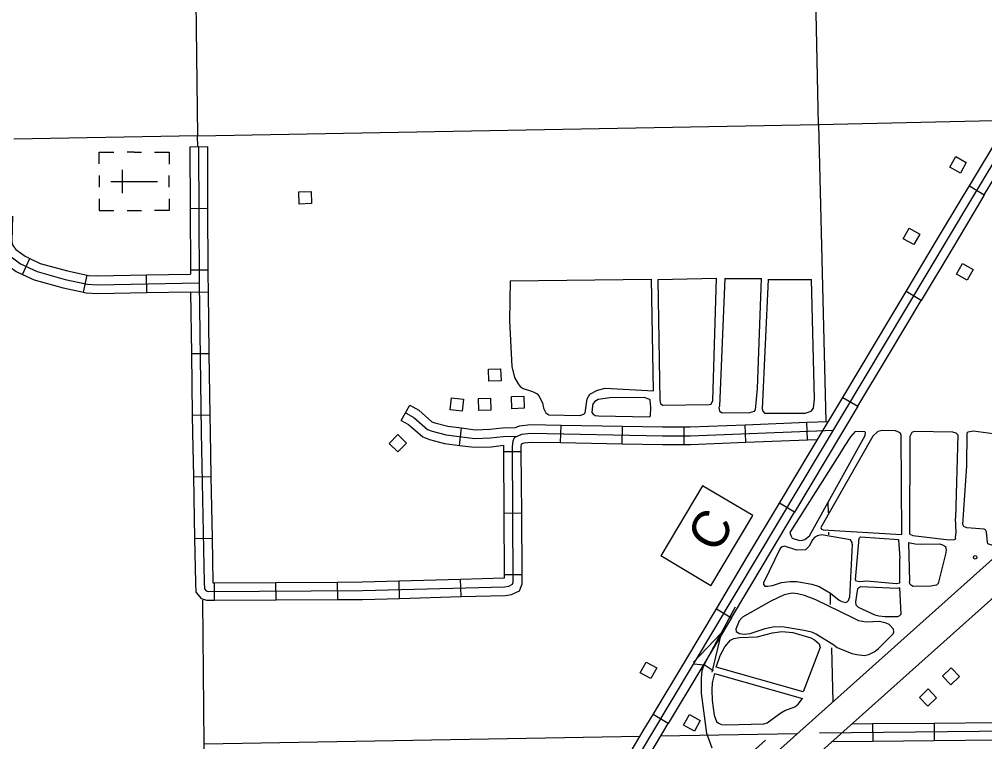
# Model space of a CAD drawing. Extents: x 1084508 to 1142749, y 1057638 to 1093403.
# Drawn here: x 1097414 to 1100010, y 1070508 to 1072452 of the extents above; entities that cross this region are included whole.
import ezdxf

# ---------------------------------------------------------------- set-up
doc = ezdxf.new("R2010")
doc.units = 0
for name, color, linetype in [('Level 15', 7, 'Continuous'), ('Level 31', 7, 'Continuous'), ('Level 32', 7, 'Continuous'), ('Level 35', 7, 'Continuous'), ('Level 43', 7, 'Continuous'), ('Level 5', 7, 'Continuous'), ('Level 56', 7, 'Continuous'), ('Level 57', 7, 'Continuous'), ('Level 58', 7, 'Continuous')]:
    doc.layers.add(name, color=color, linetype=linetype)

msp = doc.modelspace()

# ---------------------------------------------------------------- linework, layer by layer
at = {"layer": 'Level 15'}
for points in [[(1102254.8, 1073114.2), (1102246.6, 1073054.1), (1102235.2, 1073013), (1102230.6, 1072998.9), (1102210.8, 1072969.7), (1102197.7, 1072955.1), (1102173.8, 1072922.9), (1102155, 1072900), (1102143.6, 1072888.3), (1102116.9, 1072867), (1101851.5, 1072624), (1101364.1, 1072185.3), (1100217.6, 1071166.4), (1099385.1, 1070422.3)], [(1099437.4, 1070363.8), (1100269.9, 1071107.8), (1101416.4, 1072126.8), (1101904.3, 1072565.9), (1102168, 1072807.4), (1102196.3, 1072830.1), (1102213.4, 1072847.6), (1102235.6, 1072874.5), (1102258.6, 1072905.4), (1102272.7, 1072921.2), (1102301.9, 1072964.1), (1102310.4, 1072990.5), (1102323.6, 1073038.2), (1102332.6, 1073103.6)]]:
    msp.add_lwpolyline(points, dxfattribs=at)
at = {"layer": 'Level 31'}
for p, q in [((1099968.7, 1072003.9), (1100009, 1071979.6)), ((1099838.9, 1071695.2), (1099798.5, 1071719.4)), ((1099628.4, 1071434.9), (1099668.9, 1071410.7)), ((1099498.8, 1071126.2), (1099458.4, 1071150.4)), ((1099458.4, 1071150.4), (1099458.4, 1071150.4)), ((1099288.3, 1070865.9), (1099328.7, 1070841.7)), ((1099243.7, 1070699.4), (1099243.7, 1070699.4)), ((1099158.7, 1070557.2), (1099118.2, 1070581.3))]:
    msp.add_line(p, q, dxfattribs=at)
for points in [[(1098799.7, 1069999.4), (1099112.2, 1070525.3), (1099972.3, 1071964.3), (1100614.4, 1073030.4)], [(1099968.7, 1072003.9), (1100054.2, 1072145.9)], [(1100009, 1071979.6), (1100094.5, 1072121.6)], [(1099883.5, 1071861.6), (1099952.2, 1071976.4), (1099968.7, 1072003.9)], [(1100009, 1071979.6), (1099992.5, 1071952.2), (1099924, 1071837.5)], [(1099798.5, 1071719.4), (1099883.5, 1071861.6)], [(1099924, 1071837.5), (1099838.9, 1071695.2)], [(1099713.5, 1071577.1), (1099798.5, 1071719.4)], [(1099753.9, 1071553), (1099838.9, 1071695.2)], [(1099628.4, 1071434.9), (1099713.5, 1071577.1)], [(1099668.9, 1071410.7), (1099753.9, 1071553)], [(1099543.4, 1071292.6), (1099628.4, 1071434.9)], [(1099668.9, 1071410.7), (1099583.8, 1071268.4)], [(1099458.4, 1071150.4), (1099543.4, 1071292.6)], [(1099583.8, 1071268.4), (1099498.8, 1071126.2)], [(1099373.3, 1071008.1), (1099458.4, 1071150.4)], [(1099413.8, 1070983.9), (1099498.8, 1071126.2)], [(1099288.3, 1070865.9), (1099373.3, 1071008.1)], [(1099328.7, 1070841.7), (1099413.8, 1070983.9)], [(1099203.3, 1070723.6), (1099288.3, 1070865.9)], [(1099328.7, 1070841.7), (1099243.7, 1070699.4)], [(1099118.2, 1070581.3), (1099203.3, 1070723.6)], [(1099243.7, 1070699.4), (1099158.7, 1070557.2)], [(1099033.4, 1070438.9), (1099091.9, 1070537.3), (1099118.2, 1070581.3)], [(1099073.9, 1070414.8), (1099132.4, 1070513.2), (1099158.7, 1070557.2)]]:
    msp.add_lwpolyline(points, dxfattribs=at)
at = {"layer": 'Level 32'}
for p, q in [((1097872.4, 1072109.2), (1097919.4, 1072109.4)), ((1097873.1, 1071943.4), (1097920.1, 1071943.6)), ((1097422.5, 1071765.5), (1097442.3, 1071808.2)), ((1097586, 1071717.5), (1097595.9, 1071763.5)), ((1097757, 1071717), (1097756.1, 1071764.1)), ((1097873.8, 1071777.7), (1097920.9, 1071777.9)), ((1097874.3, 1071718.2), (1097921.3, 1071718.8)), ((1097876.6, 1071552.4), (1097923.7, 1071553.1)), ((1098440.7, 1071372.7), (1098463.8, 1071413.7)), ((1097878.9, 1071386.7), (1097926, 1071387.4)), ((1098597.3, 1071305.7), (1098603.1, 1071352.4)), ((1098869.6, 1071313.1), (1098870.5, 1071360.2)), ((1099035.3, 1071310.1), (1099036.2, 1071357.2)), ((1099201.5, 1071308.2), (1099201.4, 1071355.3)), ((1099368, 1071314.1), (1099366.1, 1071361.1)), ((1099533.6, 1071320.7), (1099531.7, 1071367.7)), ((1098763.8, 1071288.6), (1098716.7, 1071288.3)), ((1097881.8, 1071220.9), (1097928.8, 1071221.8)), ((1098764.8, 1071122.9), (1098717.7, 1071122.6)), ((1097884.9, 1071055.2), (1097931.9, 1071056.1)), ((1098765.7, 1070957.2), (1098718.6, 1070956.9)), ((1097938.5, 1070888.9), (1097938.3, 1070936)), ((1098104.3, 1070889.9), (1098104, 1070937)), ((1098270, 1070890.9), (1098269.7, 1070938)), ((1098436.2, 1070894.1), (1098434.9, 1070941.1)), ((1098601.9, 1070898.6), (1098600.6, 1070945.7)), ((1099708.3, 1070556), (1099708.8, 1070508.9)), ((1099874, 1070557.7), (1099874.5, 1070510.7))]:
    msp.add_line(p, q, dxfattribs=at)
for points in [[(1097872.4, 1072109.2), (1097873.1, 1071943.4)], [(1097895.9, 1072109.3), (1097897.5, 1071743.2)], [(1097919.4, 1072109.4), (1097920.1, 1071943.6)], [(1097873.1, 1071943.4), (1097873.8, 1071777.7)], [(1097920.1, 1071943.6), (1097920.9, 1071777.9)], [(1097348.6, 1071923.8), (1097346.2, 1071853.2), (1097348, 1071838.6), (1097354.3, 1071820.4), (1097371.5, 1071798.7), (1097404.9, 1071773.7), (1097422.5, 1071765.5)], [(1097395.6, 1071922.3), (1097393.4, 1071855.4), (1097394.2, 1071849.3), (1097396.2, 1071843.3), (1097404.6, 1071832.7), (1097429.1, 1071814.4), (1097442.3, 1071808.2)], [(1097388, 1071815.7), (1097417, 1071794.1), (1097461.6, 1071773.3), (1097537.3, 1071752), (1097596.7, 1071739.3), (1097623.1, 1071738), (1097897.5, 1071743.2), (1097903.1, 1071340.6), (1097910.6, 1070936.5), (1097911.5, 1070919.9), (1097916.4, 1070914.1), (1097921.2, 1070912.4), (1098336.5, 1070914.9), (1098718.9, 1070925.4), (1098730.4, 1070927), (1098740, 1070931.8), (1098742.3, 1070937.8), (1098740.2, 1071301.6), (1098741.5, 1071318.3), (1098744.1, 1071325), (1098747.1, 1071327.6), (1098765.4, 1071335.4), (1098789.8, 1071338.2), (1099143.6, 1071331.7), (1099218.6, 1071331.7), (1099603.6, 1071347)], [(1097442.3, 1071808.2), (1097469.8, 1071795.4), (1097543, 1071774.9), (1097595.9, 1071763.5)], [(1097422.5, 1071765.5), (1097453.4, 1071751.1), (1097531.7, 1071729.1), (1097586, 1071717.5)], [(1097595.9, 1071763.5), (1097599.8, 1071762.7), (1097623.5, 1071761.5), (1097756.1, 1071764.1)], [(1097756.1, 1071764.1), (1097873.8, 1071766.3)], [(1097873.8, 1071777.7), (1097873.8, 1071766.3)], [(1097920.9, 1071777.9), (1097920.7, 1071767.2)], [(1097920.7, 1071767.2), (1097921.3, 1071718.8)], [(1097586, 1071717.5), (1097593.7, 1071715.8), (1097622.8, 1071714.4), (1097757, 1071717)], [(1097757, 1071717), (1097874.3, 1071719.2), (1097874.3, 1071718.2)], [(1097874.3, 1071718.2), (1097876.6, 1071552.4)], [(1097921.3, 1071718.8), (1097923.7, 1071553.1)], [(1097923.7, 1071553.1), (1097926, 1071387.4)], [(1097876.6, 1071552.4), (1097878.9, 1071386.7)], [(1098463.8, 1071413.7), (1098487.9, 1071400.1), (1098523.4, 1071369.3), (1098531.3, 1071366.3), (1098566.3, 1071357), (1098603.1, 1071352.4)], [(1097878.9, 1071386.7), (1097879.5, 1071340.2), (1097881.8, 1071220.9)], [(1097926, 1071387.4), (1097926.6, 1071341), (1097928.8, 1071221.8)], [(1098440.7, 1071372.7), (1098460.7, 1071361.4), (1098498.9, 1071328.2), (1098517, 1071321.4), (1098557.3, 1071310.7), (1098597.3, 1071305.7)], [(1098452.2, 1071393.2), (1098474.3, 1071380.8), (1098511.1, 1071348.8), (1098524.2, 1071343.9), (1098561.8, 1071333.8), (1098639, 1071324.2), (1098680.7, 1071325.6), (1098714.8, 1071329.3), (1098751.9, 1071330.2)], [(1098603.1, 1071352.4), (1098640.1, 1071347.8), (1098679, 1071349.1), (1098713.2, 1071352.8), (1098748.2, 1071353.7)], [(1098748.2, 1071353.7), (1098759.3, 1071358.4), (1098788.7, 1071361.7), (1098870.5, 1071360.2)], [(1098870.5, 1071360.2), (1099036.2, 1071357.2)], [(1099036.2, 1071357.2), (1099143.8, 1071355.2), (1099201.4, 1071355.3)], [(1099201.4, 1071355.3), (1099218.1, 1071355.3), (1099366.1, 1071361.1)], [(1099366.1, 1071361.1), (1099531.7, 1071367.7)], [(1099531.7, 1071367.7), (1099589.7, 1071370)], [(1099368, 1071314.1), (1099533.6, 1071320.7)], [(1099533.6, 1071320.7), (1099560.8, 1071321.8)], [(1098597.3, 1071305.7), (1098638, 1071300.6), (1098682.4, 1071302.1), (1098716.9, 1071305.9)], [(1098716.7, 1071288.3), (1098716.6, 1071302.5), (1098716.9, 1071305.9)], [(1098763.8, 1071288.6), (1098763.7, 1071300.7), (1098764.4, 1071309.4), (1098771.5, 1071312.4), (1098790.9, 1071314.6), (1098869.6, 1071313.1)], [(1098869.6, 1071313.1), (1099035.3, 1071310.1)], [(1099035.3, 1071310.1), (1099143.4, 1071308.1), (1099201.5, 1071308.2)], [(1099201.5, 1071308.2), (1099219, 1071308.2), (1099368, 1071314.1)], [(1098717.7, 1071122.6), (1098716.7, 1071288.3)], [(1098764.8, 1071122.9), (1098763.8, 1071288.6)], [(1097881.8, 1071220.9), (1097884.9, 1071055.2)], [(1097928.8, 1071221.8), (1097931.9, 1071056.1)], [(1098718.6, 1070956.9), (1098717.7, 1071122.6)], [(1098765.7, 1070957.2), (1098764.8, 1071122.9)], [(1097884.9, 1071055.2), (1097887.1, 1070935.6), (1097888.4, 1070910.7), (1097902.5, 1070894.1), (1097917.1, 1070888.8), (1097938.5, 1070888.9)], [(1097931.9, 1071056.1), (1097934.1, 1070937.3), (1097934.2, 1070936), (1097938.3, 1070936)], [(1098600.6, 1070945.7), (1098716.9, 1070948.9), (1098718.7, 1070949.1), (1098718.6, 1070956.9)], [(1098601.9, 1070898.6), (1098720.9, 1070901.9), (1098737.5, 1070904.3), (1098758.7, 1070914.7), (1098765.9, 1070933.5), (1098765.7, 1070957.2)], [(1097938.3, 1070936), (1098104, 1070937)], [(1098104, 1070937), (1098269.7, 1070938)], [(1098269.7, 1070938), (1098336.1, 1070938.4), (1098434.9, 1070941.1)], [(1098434.9, 1070941.1), (1098600.6, 1070945.7)], [(1097938.5, 1070888.9), (1098104.3, 1070889.9)], [(1098104.3, 1070889.9), (1098270, 1070890.9)], [(1098270, 1070890.9), (1098336.8, 1070891.3), (1098436.2, 1070894.1)], [(1098436.2, 1070894.1), (1098601.9, 1070898.6)], [(1101200, 1070548.2), (1099566.1, 1070531)], [(1099708.3, 1070556), (1099651.8, 1070555.4)], [(1099874, 1070557.7), (1099708.3, 1070556)], [(1100039.8, 1070559.5), (1099874, 1070557.7)], [(1099708.8, 1070508.9), (1099598.4, 1070507.8)], [(1099874.5, 1070510.7), (1099708.8, 1070508.9)], [(1100040.3, 1070512.4), (1099874.5, 1070510.7)]]:
    msp.add_lwpolyline(points, dxfattribs=at)
at = {"layer": 'Level 35'}
for points in [[(1098734.2, 1071748), (1098731.8, 1071640.8), (1098738.1, 1071518), (1098745.7, 1071488.7), (1098755, 1071471.4), (1098760.9, 1071464.1), (1098768.6, 1071459), (1098793.7, 1071450.8), (1098806.1, 1071444.3), (1098811, 1071439.1), (1098820.7, 1071420.3), (1098823.7, 1071406), (1098830.1, 1071393.6), (1098837.8, 1071388.2), (1098921, 1071385.7), (1098932.2, 1071389.6), (1098935.8, 1071393.1), (1098940.8, 1071431.3), (1098948, 1071443.8), (1098969, 1071453.9), (1098989.2, 1071459.3), (1099119.3, 1071452.1), (1099114.3, 1071752.7)], [(1098734.2, 1071748), (1099114.3, 1071752.7)], [(1099131.3, 1071751.9), (1099136.2, 1071426.5), (1099138.4, 1071418.1), (1099143.6, 1071413.6), (1099268.7, 1071415.3), (1099274.6, 1071416.8), (1099279, 1071426), (1099289, 1071755.7)], [(1099131.3, 1071751.9), (1099289, 1071755.7)], [(1099310.7, 1071754.3), (1099296.8, 1071411), (1099295, 1071407.8), (1099297.2, 1071398.1), (1099304.3, 1071393.3), (1099378.6, 1071394), (1099391.3, 1071397.6), (1099393.7, 1071401.1), (1099399.3, 1071459.1), (1099409.5, 1071754.2)], [(1099310.7, 1071754.3), (1099409.5, 1071754.2)], [(1099427.4, 1071751.9), (1099411.4, 1071404.2), (1099413.6, 1071397.3), (1099418.1, 1071392.1), (1099527.3, 1071392.7), (1099543.4, 1071397.7), (1099549.7, 1071405.7), (1099552.1, 1071429.7), (1099544.2, 1071751.5)], [(1099427.4, 1071751.9), (1099544.2, 1071751.5)], [(1099108.3, 1071382.4), (1099111, 1071385), (1099112.1, 1071408.3), (1099110.6, 1071426.5), (1099109.2, 1071428.9), (1099094.6, 1071434.1), (1099002.1, 1071433.8), (1098970.9, 1071428.9), (1098961.6, 1071423.9), (1098957.4, 1071418.7), (1098955.1, 1071413), (1098953.8, 1071394.4), (1098957.4, 1071389.5), (1098962.6, 1071385.9), (1098971.1, 1071384.7)], [(1098971.1, 1071384.7), (1099108.3, 1071382.4)], [(1099784.1, 1071335), (1099782.7, 1071339.6), (1099770, 1071344.8), (1099735.4, 1071345.9), (1099722.7, 1071342.6), (1099709.3, 1071330.8), (1099569.7, 1071085), (1099570.8, 1071080.3), (1099575.6, 1071078.3), (1099785.9, 1071066)], [(1099661.4, 1071342.6), (1099648.7, 1071328.7), (1099632.3, 1071302.7), (1099619.1, 1071281.7), (1099486.3, 1071071)], [(1099486.3, 1071071), (1099488.2, 1071063.3), (1099492.5, 1071055.8), (1099512.2, 1071049.6), (1099519.7, 1071050.2), (1099526.5, 1071052.6), (1099539.1, 1071062.7), (1099688.5, 1071332.2), (1099689.8, 1071340.1), (1099687.8, 1071342.5), (1099661.4, 1071342.6)], [(1099784.1, 1071335), (1099785.9, 1071066)], [(1099937.3, 1071333.6), (1099933.6, 1071338.5), (1099924.4, 1071341.3), (1099820.5, 1071343.4), (1099814.4, 1071340.4), (1099808.8, 1071329.5), (1099807.4, 1071068.9), (1099808.8, 1071066.4), (1099816.7, 1071062.9), (1099914.7, 1071051.5), (1099929.1, 1071052.3), (1099932.5, 1071054.6), (1099931.4, 1071057.4), (1099933.1, 1071071.6), (1099931.9, 1071109.6)], [(1099937.3, 1071333.6), (1099931.9, 1071109.6)], [(1100077.1, 1071054.2), (1100075.5, 1071045.1), (1100070.6, 1071041.1), (1100064.1, 1071039), (1100031.6, 1071036.3), (1100018.6, 1071040.6), (1100017.2, 1071044), (1100014.7, 1071072.8), (1100012, 1071078.4), (1100008.5, 1071080.5), (1099962.2, 1071083.9), (1099954.3, 1071087.4), (1099950.9, 1071092.9), (1099961.7, 1071250.3), (1099962.8, 1071339.2), (1099965.2, 1071341.8), (1099978.6, 1071344.7), (1100059.9, 1071334), (1100064.8, 1071327.9), (1100067.5, 1071312.6)], [(1099653.4, 1071040.1), (1099653.6, 1071043.9), (1099649, 1071051.3), (1099570.7, 1071065.2), (1099560.4, 1071062.4), (1099553, 1071058.3), (1099547.3, 1071051.6), (1099538.1, 1071034.6), (1099527.8, 1071024.8), (1099504.6, 1071023.7), (1099471.3, 1071034.4), (1099465.2, 1071032.6), (1099459.7, 1071028.6)], [(1099781.8, 1070935.2), (1099771.5, 1070933), (1099693.4, 1070940.4), (1099673.7, 1070938.4), (1099665.5, 1070940.7), (1099662.3, 1070943.7), (1099672.6, 1071056.1), (1099675.7, 1071059.7), (1099777.9, 1071052.2), (1099781.8, 1071001.1)], [(1099653.4, 1071040.1), (1099646, 1070896.7)], [(1099805, 1071044.2), (1099823.3, 1071040.8), (1099838.7, 1071040.1), (1099888.3, 1071040.8), (1099896.8, 1071038.3), (1099904.2, 1071033.5), (1099906.1, 1071024.1), (1099904.9, 1071013.1), (1099884.6, 1070933.9), (1099880.4, 1070929.7), (1099865.4, 1070926.7), (1099817.8, 1070925.7), (1099813, 1070928.4), (1099809, 1070933.2), (1099807.9, 1070939.8)], [(1099805, 1071044.2), (1099807.9, 1070939.8)], [(1099459.7, 1071028.6), (1099415.4, 1070936.2)], [(1099781.8, 1070935.2), (1099781.8, 1071001.1)], [(1099415.4, 1070936.2), (1099415.4, 1070931.2), (1099418.9, 1070926.8), (1099426.3, 1070926.4), (1099439.1, 1070928.6), (1099463.6, 1070936.9), (1099487, 1070939.6), (1099504.9, 1070939.6), (1099544.7, 1070932.2), (1099565, 1070925.9), (1099595.7, 1070908.2), (1099618.6, 1070889.5), (1099626, 1070885.3), (1099636.7, 1070883.2), (1099640.1, 1070884.6), (1099643.4, 1070888.7), (1099646, 1070896.7)], [(1099657.3, 1070840.3), (1099555.9, 1070890.1), (1099525.4, 1070901.6), (1099506.7, 1070906.3), (1099491.9, 1070908), (1099470.8, 1070903.2), (1099434.6, 1070886.9), (1099358.6, 1070843.5), (1099349.5, 1070833.4), (1099340.5, 1070811.5), (1099341.6, 1070805.2), (1099350.6, 1070799.9), (1099362.9, 1070797.8), (1099378.8, 1070799.9), (1099419.2, 1070812.6), (1099444.7, 1070818.2), (1099470.5, 1070817.5), (1099524.4, 1070808.6), (1099544.1, 1070803.6), (1099557.7, 1070797.8), (1099602, 1070770.4), (1099613.6, 1070761.9)], [(1099781.9, 1070922), (1099774.4, 1070920.8), (1099676.4, 1070924.7), (1099667.8, 1070920), (1099662.1, 1070884.4), (1099663.3, 1070876.2), (1099669.8, 1070869.9), (1099714.4, 1070849.4), (1099725.1, 1070846.6), (1099742.7, 1070845.3), (1099776.6, 1070845.2), (1099782.2, 1070847.9), (1099784.9, 1070851.8)], [(1099784.9, 1070851.8), (1099781.9, 1070922)], [(1099763.8, 1070798.3), (1099765.7, 1070804.3), (1099764.3, 1070811.5), (1099753.2, 1070823.9), (1099744.9, 1070827.7), (1099726.9, 1070832.2), (1099691.5, 1070830.3), (1099671.3, 1070833.7), (1099657.3, 1070840.3)], [(1099287.4, 1070709.3), (1099298.9, 1070740.2), (1099311.3, 1070763.2), (1099326.4, 1070781.6), (1099335, 1070786), (1099350.3, 1070789), (1099398.3, 1070790.7), (1099439.3, 1070801.5), (1099464.6, 1070805.2), (1099493.6, 1070802.1), (1099542, 1070787.7), (1099552.3, 1070782.7), (1099564.5, 1070771.5), (1099567.4, 1070761.6), (1099521.8, 1070642.3)], [(1099723.7, 1070758.3), (1099763.8, 1070798.3)], [(1099613.6, 1070761.9), (1099652.5, 1070745.6), (1099666.4, 1070742.9), (1099685.4, 1070740.3), (1099698.5, 1070743.3), (1099713.1, 1070750.3), (1099723.7, 1070758.3)], [(1099521.8, 1070642.3), (1099287.4, 1070709.3)], [(1099283.6, 1070691.5), (1099276.9, 1070666.8), (1099275.9, 1070647.9), (1099277.2, 1070619.4), (1099282.6, 1070580), (1099288.8, 1070562.9), (1099294, 1070557.8), (1099302, 1070554.6), (1099314.8, 1070553.8), (1099416.1, 1070556), (1099425.1, 1070558.8), (1099461.5, 1070585.8), (1099472.9, 1070592.1), (1099499.3, 1070602.1), (1099508.4, 1070609.7), (1099520.2, 1070624.8)], [(1099283.6, 1070691.5), (1099520.2, 1070624.8)]]:
    msp.add_lwpolyline(points, dxfattribs=at)
at = {"layer": 'Level 43'}
for p, q in [((1099301.4, 1070800.5), (1099227.2, 1070722.4)), ((1099301.4, 1070800.5), (1099276.2, 1070695.7)), ((1099226.7, 1070717.5), (1099255.3, 1070715.5)), ((1099279.5, 1070699.4), (1099255.7, 1070715.4))]:
    msp.add_line(p, q, dxfattribs=at)
for points in [[(1099277.4, 1070491), (1099262.3, 1070530.1), (1099248.3, 1070639.2), (1099248, 1070656.8), (1099248.2, 1070679.1), (1099250.6, 1070701.1), (1099256, 1070717), (1099339.7, 1070870.9)], [(1099321.2, 1070836.9), (1099339.7, 1070870.9)], [(1099249.3, 1070688.7), (1099250.6, 1070701.1), (1099256, 1070717), (1099301.4, 1070800.5)], [(1099264.5, 1070524.3), (1099262.3, 1070530.1), (1099248.3, 1070639.2), (1099248.2, 1070647.3)]]:
    msp.add_lwpolyline(points, dxfattribs=at)
at = {"layer": 'Level 5'}
for points in [[(1099563, 1072169.2), (1099541.5, 1073199.5)], [(1097885, 1072788.4), (1097893, 1072138.7)], [(1097893.4, 1072109.2), (1097893, 1072138.7), (1099563, 1072169.2), (1100075.3, 1072180.9)], [(1099563, 1072169.2), (1099582.6, 1071369.8)], [(1097893, 1072138.7), (1097399.1, 1072129.9)], [(1099588, 1071151), (1099588.7, 1071124.3)], [(1099590, 1071072.5), (1099590.1, 1071064.7)], [(1099594, 1070906.1), (1099594.8, 1070877.1)], [(1097909.5, 1070097.5), (1097911, 1070502), (1097906.8, 1070889)], [(1099597.6, 1070760.8), (1099601.2, 1070615.5)], [(1099083, 1070522.3), (1097911, 1070502)], [(1099505.2, 1070529.6), (1099138.4, 1070523.3)]]:
    msp.add_lwpolyline(points, dxfattribs=at)
at = {"layer": 'Level 56'}
msp.add_line((1099340, 1070441), (1099420.2, 1070512.3), dxfattribs=at)
for points in [[(1099944.7, 1072038.2), (1099916.1, 1072054.2), (1099932.1, 1072082.8), (1099960.6, 1072066.8)], [(1098166.7, 1071955), (1098165.6, 1071987.7), (1098198.3, 1071988.8), (1098199.4, 1071956.2)], [(1099819.3, 1071845.7), (1099790.7, 1071861.6), (1099806.7, 1071890.2), (1099835.2, 1071874.3)], [(1099963.1, 1071750.6), (1099934.6, 1071766.5), (1099950.6, 1071795.1), (1099979.1, 1071779.2)], [(1098676.5, 1071478.2), (1098675.4, 1071510.8), (1098708.1, 1071512), (1098709.2, 1071479.3)], [(1098572.4, 1071401.1), (1098575.7, 1071433.6), (1098608.3, 1071430.3), (1098605, 1071397.8)], [(1098649.3, 1071399.2), (1098648.2, 1071431.8), (1098680.9, 1071432.9), (1098682, 1071400.3)], [(1098738.5, 1071404.3), (1098737.4, 1071436.9), (1098770.1, 1071438), (1098771.2, 1071405.4)], [(1098408.6, 1071311.1), (1098431.4, 1071334.5), (1098454.8, 1071311.6), (1098432, 1071288.2)], [(1099112.2, 1070678), (1099083.5, 1070693.6), (1099099.2, 1070722.4), (1099127.9, 1070706.7)], [(1099918.9, 1070661.3), (1099896.3, 1070684.9), (1099920.1, 1070707.5), (1099942.6, 1070683.8)], [(1099856.9, 1070604), (1099834.4, 1070627.7), (1099858.1, 1070650.3), (1099880.6, 1070626.6)], [(1099229.1, 1070537), (1099200.4, 1070552.6), (1099216, 1070581.4), (1099244.7, 1070565.8)]]:
    msp.add_lwpolyline(points, close=True, dxfattribs=at)
at = {"layer": 'Level 57'}
for p, q in [((1097722.7, 1072094.2), (1097703.4, 1072094.2)), ((1097722.7, 1072094.2), (1097742.6, 1072094.2)), ((1097691.3, 1071984.4), (1097691.3, 1072047.4)), ((1097628.5, 1072031.7), (1097628.5, 1072000.3)), ((1097816.8, 1072000.1), (1097816.8, 1072031.5)), ((1097659.9, 1072015.8), (1097785.4, 1072015.7)), ((1097722.7, 1072015.7), (1097722.7, 1072015.7)), ((1097722.7, 1072015.7), (1097722.7, 1072015.7)), ((1097703.3, 1071937.3), (1097742.5, 1071937.3)), ((1099251.3, 1071197.2), (1099138.6, 1071008.6)), ((1099386, 1071116.7), (1099251.3, 1071197.2)), ((1099273.3, 1070928.1), (1099386, 1071116.7)), ((1099273.3, 1070928.1), (1099138.6, 1071008.6))]:
    msp.add_line(p, q, dxfattribs=at)
for points in [[(1097628.5, 1072062.9), (1097628.6, 1072094.3), (1097667.8, 1072094.3)], [(1097777.7, 1072094.2), (1097816.9, 1072094.1), (1097816.9, 1072062.7)], [(1097628.5, 1071968.7), (1097628.4, 1071937.3), (1097667.7, 1071937.3)], [(1097816.8, 1071968.6), (1097816.8, 1071937.2), (1097777.5, 1071937.2)]]:
    msp.add_lwpolyline(points, dxfattribs=at)
at = {"layer": 'Level 58'}
msp.add_circle((1099984.3, 1071004.3), 4.71, dxfattribs=at)

# ---------------------------------------------------------------- texts
at = {"layer": 'Level 57'}
msp.add_text('C', height=99.4, rotation=59.1302, dxfattribs=at).set_placement((1099289.9, 1071012))

doc.saveas('drawing.dxf')
